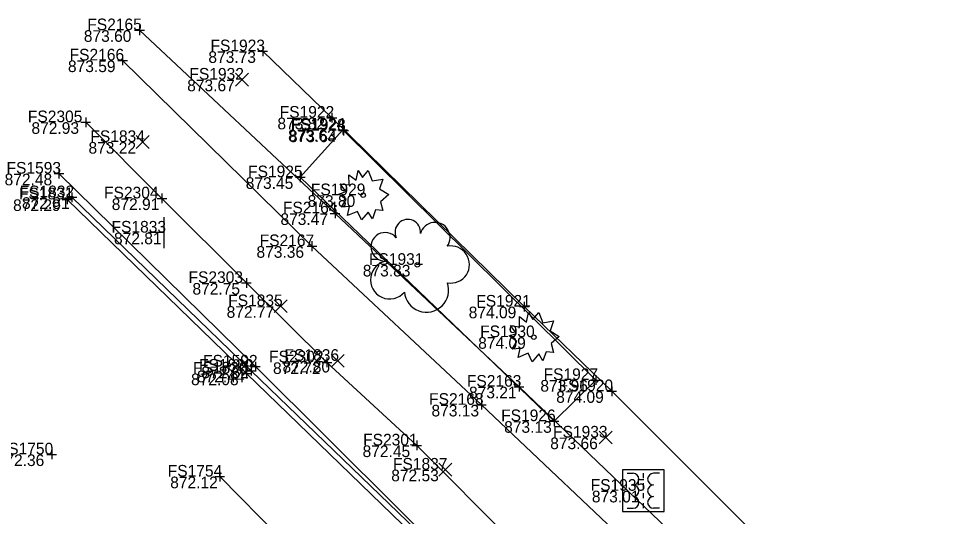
# Model space of a CAD drawing. Extents: x 1479420 to 1479833, y 379731 to 380103.
# Drawn here: x 1479498.2 to 1479593, y 380051.7 to 380103.1 of the extents above; entities that cross this region are included whole.
import ezdxf

# ---------------------------------------------------------------- set-up
doc = ezdxf.new("R2010")
doc.units = 0
for name, color, linetype in [('PM_X_Lane_Line', 7, 'Continuous'), ('PV_X_Curb', 7, 'Continuous'), ('PV_X_Walk', 7, 'Continuous'), ('SN_X_Public', 7, 'Continuous'), ('SV_X_Random_Point', 7, 'Continuous'), ('SV_X_Shot_Marker', 7, 'Continuous'), ('SV_X_Text_Elevation', 7, 'Continuous'), ('SV_X_Text_Name', 7, 'Continuous'), ('UT_X_Electric_Cells', 7, 'Continuous'), ('UT_X_Gas', 7, 'Continuous'), ('UT_X_Water', 7, 'Continuous'), ('VG_X_Cells', 7, 'Continuous'), ('VG_X_Flower_Bed', 7, 'Continuous')]:
    doc.layers.add(name, color=color, linetype=linetype)

msp = doc.modelspace()

# ---------------------------------------------------------------- linework, layer by layer
at = {"layer": 'PM_X_Lane_Line'}
msp.add_line((1479518.914, 380055.834), (1479525.775, 380048.891), dxfattribs=at)
at = {"layer": 'PV_X_Curb'}
for points in [[(1479795.994, 380033.189), (1479773.609, 380022.189), (1479753.08, 380012.28), (1479732.582, 380002.187), (1479709.578, 379990.944), (1479686.038, 379979.568), (1479675.424, 379995.638), (1479673.845, 379997.042), (1479672.388, 379997.402), (1479671.072, 379997.477), (1479668.749, 379997.507), (1479666.577, 379997.444), (1479665.261, 379997.435), (1479663.761, 379996.907), (1479662.621, 379996.118), (1479646.813, 379979.589), (1479631.39, 379994.413), (1479612.948, 380012.393), (1479594.615, 380030.048), (1479574.047, 380049.976), (1479559.355, 380064.639), (1479550.33, 380073.358), (1479530.481, 380092.839), (1479523.351, 380099.687)], [(1479620.557, 379971.482), (1479582.44, 380008.391), (1479569.122, 380021.057), (1479556.793, 380033.025), (1479540.187, 380049.375), (1479522.156, 380066.75), (1479503.679, 380084.635)], [(1479602.178, 379989.373), (1479582.142, 380008.015), (1479568.704, 380020.876), (1479556.358, 380032.756), (1479539.916, 380048.835), (1479521.67, 380066.459), (1479503.182, 380084.417)]]:
    msp.add_lwpolyline(points, dxfattribs=at)
at = {"layer": 'PV_X_Walk'}
for points in [[(1479608.139, 380010.055), (1479588.42, 380028.534), (1479565.918, 380049.66), (1479549.795, 380065.102), (1479530.811, 380082.977), (1479510.647, 380101.859)], [(1479508.898, 380098.739), (1479528.424, 380079.592), (1479545.906, 380063.234), (1479563.416, 380046.674), (1479583.683, 380027.557), (1479601.433, 380010.982), (1479618.885, 379994.721), (1479633.506, 379980.864), (1479639.156, 379975.367), (1479642.136, 379972.51), (1479646.219, 379969.763), (1479649.18, 379968.041), (1479652.865, 379966.819), (1479656.787, 379966.268), (1479660.633, 379966.347), (1479661.26, 379962.343), (1479661.797, 379958.407), (1479662.398, 379954.371), (1479663.052, 379950.601), (1479663.586, 379946.455), (1479663.663, 379946.474), (1479664.156, 379942.194)]]:
    msp.add_lwpolyline(points, dxfattribs=at)
at = {"layer": 'SN_X_Public'}
for p, q in [((1479513.166, 380082.593), (1479513.166, 380079.393)), ((1479513.166, 380080.993), (1479511.566, 380080.993))]:
    msp.add_line(p, q, dxfattribs=at)
at = {"layer": 'SV_X_Random_Point'}
for p, q in [((1479520.54, 380096.096), (1479521.874, 380097.431)), ((1479520.54, 380097.431), (1479521.874, 380096.096)), ((1479510.31, 380089.661), (1479511.644, 380090.996)), ((1479510.31, 380090.996), (1479511.644, 380089.661)), ((1479524.529, 380072.736), (1479525.863, 380074.071)), ((1479524.529, 380074.071), (1479525.863, 380072.736)), ((1479530.416, 380067.103), (1479531.75, 380068.438)), ((1479530.416, 380068.438), (1479531.75, 380067.103)), ((1479558.052, 380059.194), (1479559.386, 380060.529)), ((1479558.052, 380060.529), (1479559.386, 380059.194)), ((1479541.524, 380055.885), (1479542.858, 380057.22)), ((1479541.524, 380057.22), (1479542.858, 380055.885))]:
    msp.add_line(p, q, dxfattribs=at)
at = {"layer": 'SV_X_Shot_Marker'}
for p, q in [((1479510.147, 380101.859), (1479511.147, 380101.859)), ((1479510.647, 380102.359), (1479510.647, 380101.359)), ((1479510.647, 380101.859), (1479510.647, 380101.859)), ((1479522.851, 380099.687), (1479523.851, 380099.687)), ((1479523.351, 380100.187), (1479523.351, 380099.187)), ((1479523.351, 380099.687), (1479523.351, 380099.687)), ((1479508.398, 380098.739), (1479509.398, 380098.739)), ((1479508.898, 380099.239), (1479508.898, 380098.239)), ((1479508.898, 380098.739), (1479508.898, 380098.739)), ((1479530.481, 380093.339), (1479530.481, 380092.339)), ((1479504.605, 380092.371), (1479505.605, 380092.371)), ((1479505.105, 380092.871), (1479505.105, 380091.871)), ((1479505.105, 380092.371), (1479505.105, 380092.371)), ((1479529.981, 380092.839), (1479530.981, 380092.839)), ((1479530.481, 380092.839), (1479530.481, 380092.839)), ((1479531.612, 380092.101), (1479531.612, 380091.101)), ((1479531.112, 380091.601), (1479532.112, 380091.601)), ((1479531.19, 380091.516), (1479532.19, 380091.516)), ((1479531.612, 380091.601), (1479531.612, 380091.601)), ((1479531.69, 380092.016), (1479531.69, 380091.016)), ((1479531.69, 380091.516), (1479531.69, 380091.516)), ((1479502.338, 380087.571), (1479502.338, 380086.571)), ((1479501.838, 380087.071), (1479502.838, 380087.071)), ((1479502.338, 380087.071), (1479502.338, 380087.071)), ((1479526.73, 380086.697), (1479527.73, 380086.697)), ((1479527.23, 380087.197), (1479527.23, 380086.197)), ((1479527.23, 380086.697), (1479527.23, 380086.697)), ((1479503.179, 380084.635), (1479504.179, 380084.635)), ((1479503.182, 380084.917), (1479503.182, 380083.917)), ((1479503.679, 380085.135), (1479503.679, 380084.135)), ((1479503.679, 380084.635), (1479503.679, 380084.635)), ((1479512.451, 380084.517), (1479513.451, 380084.517)), ((1479512.951, 380085.017), (1479512.951, 380084.017)), ((1479512.951, 380084.517), (1479512.951, 380084.517)), ((1479502.682, 380084.417), (1479503.682, 380084.417)), ((1479503.182, 380084.417), (1479503.182, 380084.417)), ((1479530.311, 380082.977), (1479531.311, 380082.977)), ((1479530.811, 380083.477), (1479530.811, 380082.477)), ((1479530.811, 380082.977), (1479530.811, 380082.977)), ((1479528.424, 380080.092), (1479528.424, 380079.092)), ((1479527.924, 380079.592), (1479528.924, 380079.592)), ((1479528.424, 380079.592), (1479528.424, 380079.592)), ((1479521.671, 380076.294), (1479521.671, 380075.294)), ((1479521.171, 380075.794), (1479522.171, 380075.794)), ((1479521.671, 380075.794), (1479521.671, 380075.794)), ((1479549.83, 380073.358), (1479550.83, 380073.358)), ((1479550.33, 380073.858), (1479550.33, 380072.858)), ((1479550.33, 380073.358), (1479550.33, 380073.358)), ((1479522.598, 380067.681), (1479522.598, 380066.681)), ((1479529.469, 380067.611), (1479530.469, 380067.611)), ((1479529.969, 380068.111), (1479529.969, 380067.111)), ((1479529.969, 380067.611), (1479529.969, 380067.611)), ((1479521.656, 380066.75), (1479522.656, 380066.75)), ((1479521.67, 380066.959), (1479521.67, 380065.959)), ((1479522.098, 380067.181), (1479523.098, 380067.181)), ((1479522.156, 380067.25), (1479522.156, 380066.25)), ((1479522.156, 380066.75), (1479522.156, 380066.75)), ((1479522.598, 380067.181), (1479522.598, 380067.181)), ((1479521.17, 380066.459), (1479522.17, 380066.459)), ((1479521.67, 380066.459), (1479521.67, 380066.459)), ((1479549.795, 380065.602), (1479549.795, 380064.602)), ((1479557.202, 380065.792), (1479558.202, 380065.792)), ((1479557.702, 380066.292), (1479557.702, 380065.292)), ((1479557.702, 380065.792), (1479557.702, 380065.792)), ((1479549.295, 380065.102), (1479550.295, 380065.102)), ((1479549.795, 380065.102), (1479549.795, 380065.102)), ((1479558.855, 380064.639), (1479559.855, 380064.639)), ((1479559.355, 380065.139), (1479559.355, 380064.139)), ((1479559.355, 380064.639), (1479559.355, 380064.639)), ((1479545.906, 380063.734), (1479545.906, 380062.734)), ((1479545.406, 380063.234), (1479546.406, 380063.234)), ((1479545.906, 380063.234), (1479545.906, 380063.234)), ((1479553.402, 380062.048), (1479553.402, 380061.048)), ((1479552.902, 380061.548), (1479553.902, 380061.548)), ((1479553.402, 380061.548), (1479553.402, 380061.548)), ((1479538.745, 380059.043), (1479539.745, 380059.043)), ((1479539.245, 380059.543), (1479539.245, 380058.543)), ((1479539.245, 380059.043), (1479539.245, 380059.043)), ((1479501.096, 380058.122), (1479502.096, 380058.122)), ((1479501.596, 380058.622), (1479501.596, 380057.622)), ((1479501.596, 380058.122), (1479501.596, 380058.122)), ((1479518.914, 380056.334), (1479518.914, 380055.334)), ((1479518.414, 380055.834), (1479519.414, 380055.834)), ((1479518.914, 380055.834), (1479518.914, 380055.834))]:
    msp.add_line(p, q, dxfattribs=at)
at = {"layer": 'UT_X_Electric_Cells'}
for p, q in [((1479560.928, 380056.17), (1479561.549, 380056.17)), ((1479562.599, 380056.17), (1479562.599, 380055.656)), ((1479564.27, 380056.17), (1479563.649, 380056.17)), ((1479562.599, 380055.142), (1479562.599, 380054.627)), ((1479562.599, 380054.37), (1479562.599, 380054.37)), ((1479562.599, 380054.113), (1479562.599, 380053.599)), ((1479560.928, 380052.57), (1479561.549, 380052.57)), ((1479562.599, 380053.084), (1479562.599, 380052.57)), ((1479564.27, 380052.57), (1479563.649, 380052.57))]:
    msp.add_line(p, q, dxfattribs=at)
msp.add_lwpolyline([(1479560.449, 380052.22), (1479564.749, 380052.22), (1479564.749, 380056.52), (1479560.449, 380056.52)], close=True, dxfattribs=at)
for centre, start, end in [((1479561.549, 380055.57), 270, 90), ((1479563.649, 380055.57), 90, 270), ((1479561.549, 380054.37), 270, 90), ((1479563.649, 380054.37), 90, 270), ((1479561.549, 380053.17), 270, 90), ((1479563.649, 380053.17), 90, 270)]:
    msp.add_arc(centre, 0.6, start, end, dxfattribs=at)
at = {"layer": 'UT_X_Gas'}
msp.add_lwpolyline([(1479505.105, 380092.371), (1479512.951, 380084.517), (1479521.671, 380075.794), (1479529.969, 380067.611), (1479539.245, 380059.043), (1479549.105, 380049.154), (1479558.282, 380040.003), (1479562.889, 380034.62), (1479568.453, 380028.062), (1479574.471, 380021.4), (1479579.923, 380015.798), (1479590.076, 380006.869), (1479598.835, 379999.983)], dxfattribs=at)
at = {"layer": 'UT_X_Water'}
msp.add_lwpolyline([(1479502.338, 380087.071), (1479522.598, 380067.181), (1479544.961, 380044.963), (1479586.915, 380004.501), (1479604.754, 379987.567)], dxfattribs=at)
at = {"layer": 'VG_X_Cells'}
for points in [[(1479533.63, 380086.656), (1479534.235, 380087.391), (1479534.65, 380086.337), (1479535.742, 380086.517), (1479535.403, 380085.506), (1479536.348, 380084.911), (1479535.492, 380084.176), (1479535.742, 380083.262), (1479534.988, 380083.331), (1479534.663, 380082.417), (1479534.235, 380083.109), (1479533.557, 380082.292), (1479533.128, 380083.179), (1479532.108, 380082.749), (1479532.3, 380083.691), (1479531.488, 380083.607), (1479531.962, 380084.397), (1479531.193, 380084.966), (1479531.932, 380085.229), (1479531.325, 380086.032), (1479532.257, 380085.922), (1479532.227, 380086.961), (1479532.98, 380086.392), (1479533.187, 380087.377), (1479533.63, 380086.656)], [(1479551.223, 380072.02), (1479551.828, 380072.755), (1479552.243, 380071.702), (1479553.335, 380071.882), (1479552.996, 380070.87), (1479553.941, 380070.275), (1479553.085, 380069.54), (1479553.335, 380068.627), (1479552.581, 380068.695), (1479552.256, 380067.782), (1479551.828, 380068.474), (1479551.15, 380067.657), (1479550.721, 380068.544), (1479549.701, 380068.114), (1479549.893, 380069.055), (1479549.081, 380068.972), (1479549.555, 380069.762), (1479548.786, 380070.33), (1479549.525, 380070.594), (1479548.918, 380071.397), (1479549.85, 380071.287), (1479549.82, 380072.325), (1479550.573, 380071.757), (1479550.78, 380072.742), (1479551.223, 380072.02)]]:
    msp.add_lwpolyline(points, dxfattribs=at)
for centre, radius in [((1479533.714, 380084.846), 0.23), ((1479539.298, 380077.666), 0.24), ((1479551.307, 380070.211), 0.23)]:
    msp.add_circle(centre, radius, dxfattribs=at)
for centre, radius, start, end in [((1479538.314, 380081.034), 1.317, 354.0047, 205.97412), ((1479541.124, 380080.495), 1.553, 323.82996, 165.0376), ((1479535.989, 380079.53), 1.471, 39.06254, 279.54124), ((1479542.758, 380077.702), 1.915, 259.14531, 101.45961), ((1479536.445, 380076.118), 1.974, 96.17219, 320.57371), ((1479540.244, 380075.061), 2.284, 184.94757, 19.45715)]:
    msp.add_arc(centre, radius, start, end, dxfattribs=at)
at = {"layer": 'VG_X_Flower_Bed'}
msp.add_lwpolyline([(1479531.612, 380091.601), (1479527.23, 380086.697), (1479553.402, 380061.548), (1479557.702, 380065.792), (1479531.69, 380091.516)], dxfattribs=at)

# ---------------------------------------------------------------- texts
at = {"layer": 'SV_X_Text_Elevation'}
for s, p in [('873.60', (1479504.902, 380100.659)), ('873.73', (1479517.748, 380098.487)), ('873.59', (1479503.267, 380097.539)), ('873.67', (1479515.566, 380095.564)), ('872.93', (1479499.502, 380091.171)), ('873.82', (1479524.869, 380091.639)), ('873.63', (1479525.971, 380090.401)), ('873.64', (1479526.059, 380090.316)), ('873.22', (1479505.384, 380089.129)), ('872.48', (1479496.735, 380085.871)), ('873.45', (1479521.599, 380085.497)), ('872.81', (1479498.529, 380083.435)), ('872.91', (1479507.782, 380083.317)), ('873.80', (1479527.989, 380083.646)), ('872.29', (1479497.608, 380083.217)), ('873.47', (1479525.18, 380081.777)), ('872.81', (1479508.016, 380079.793)), ('873.36', (1479522.708, 380078.392)), ('873.83', (1479533.676, 380076.466)), ('872.75', (1479516.106, 380074.594)), ('872.77', (1479519.631, 380072.203)), ('874.09', (1479544.595, 380072.158)), ('874.09', (1479545.573, 380069.01)), ('872.72', (1479524.413, 380066.411)), ('872.80', (1479525.395, 380066.57)), ('872.44', (1479516.572, 380065.55)), ('872.52', (1479517.024, 380065.981)), ('872.08', (1479515.963, 380065.259)), ('873.96', (1479551.986, 380064.592)), ('873.21', (1479544.626, 380063.902)), ('874.09', (1479553.62, 380063.439)), ('873.13', (1479540.757, 380062.034)), ('873.13', (1479548.253, 380060.348)), ('873.66', (1479553.003, 380058.662)), ('872.45', (1479533.652, 380057.843)), ('872.36', (1479495.918, 380056.922)), ('872.53', (1479536.607, 380055.352)), ('872.12', (1479513.813, 380054.634)), ('873.01', (1479557.298, 380053.17))]:
    msp.add_text(s, height=1.2, dxfattribs=at).set_placement(p)
at = {"layer": 'SV_X_Text_Name'}
for s, p in [('FS2165', (1479505.262, 380101.859)), ('FS1923', (1479517.966, 380099.687)), ('FS2166', (1479503.438, 380098.739)), ('FS1932', (1479515.794, 380096.764)), ('FS1922', (1479525.106, 380092.839)), ('FS2305', (1479499.134, 380092.371)), ('FS1924', (1479526.237, 380091.601)), ('FS1928', (1479526.296, 380091.516)), ('FS1834', (1479505.583, 380090.329)), ('FS1593', (1479496.934, 380087.071)), ('FS1925', (1479521.845, 380086.697)), ('FS1831', (1479498.212, 380084.417)), ('FS1832', (1479498.285, 380084.635)), ('FS2304', (1479506.989, 380084.517)), ('FS1929', (1479528.321, 380084.846)), ('FS2164', (1479525.436, 380082.977)), ('FS1833', (1479507.762, 380080.993)), ('FS2167', (1479523.039, 380079.592)), ('FS1931', (1479534.309, 380077.666)), ('FS2303', (1479515.7, 380075.794)), ('FS1835', (1479519.792, 380073.403)), ('FS1921', (1479545.379, 380073.358)), ('FS1930', (1479545.781, 380070.21)), ('FS1592', (1479517.204, 380067.181)), ('FS2302', (1479524.007, 380067.611)), ('FS1836', (1479525.604, 380067.77)), ('FS1830', (1479516.162, 380066.459)), ('FS1829', (1479516.781, 380066.75)), ('FS1927', (1479552.317, 380065.792)), ('FS2163', (1479544.41, 380065.102)), ('FS1920', (1479553.866, 380064.639)), ('FS2168', (1479540.512, 380063.234)), ('FS1926', (1479547.942, 380061.548)), ('FS1933', (1479553.296, 380059.862)), ('FS2301', (1479533.708, 380059.043)), ('FS1750', (1479496.126, 380058.122)), ('FS1754', (1479513.558, 380055.834)), ('FS1837', (1479536.787, 380056.552)), ('FS1935', (1479557.176, 380054.37))]:
    msp.add_text(s, height=1.2, dxfattribs=at).set_placement(p)

doc.saveas('drawing.dxf')
